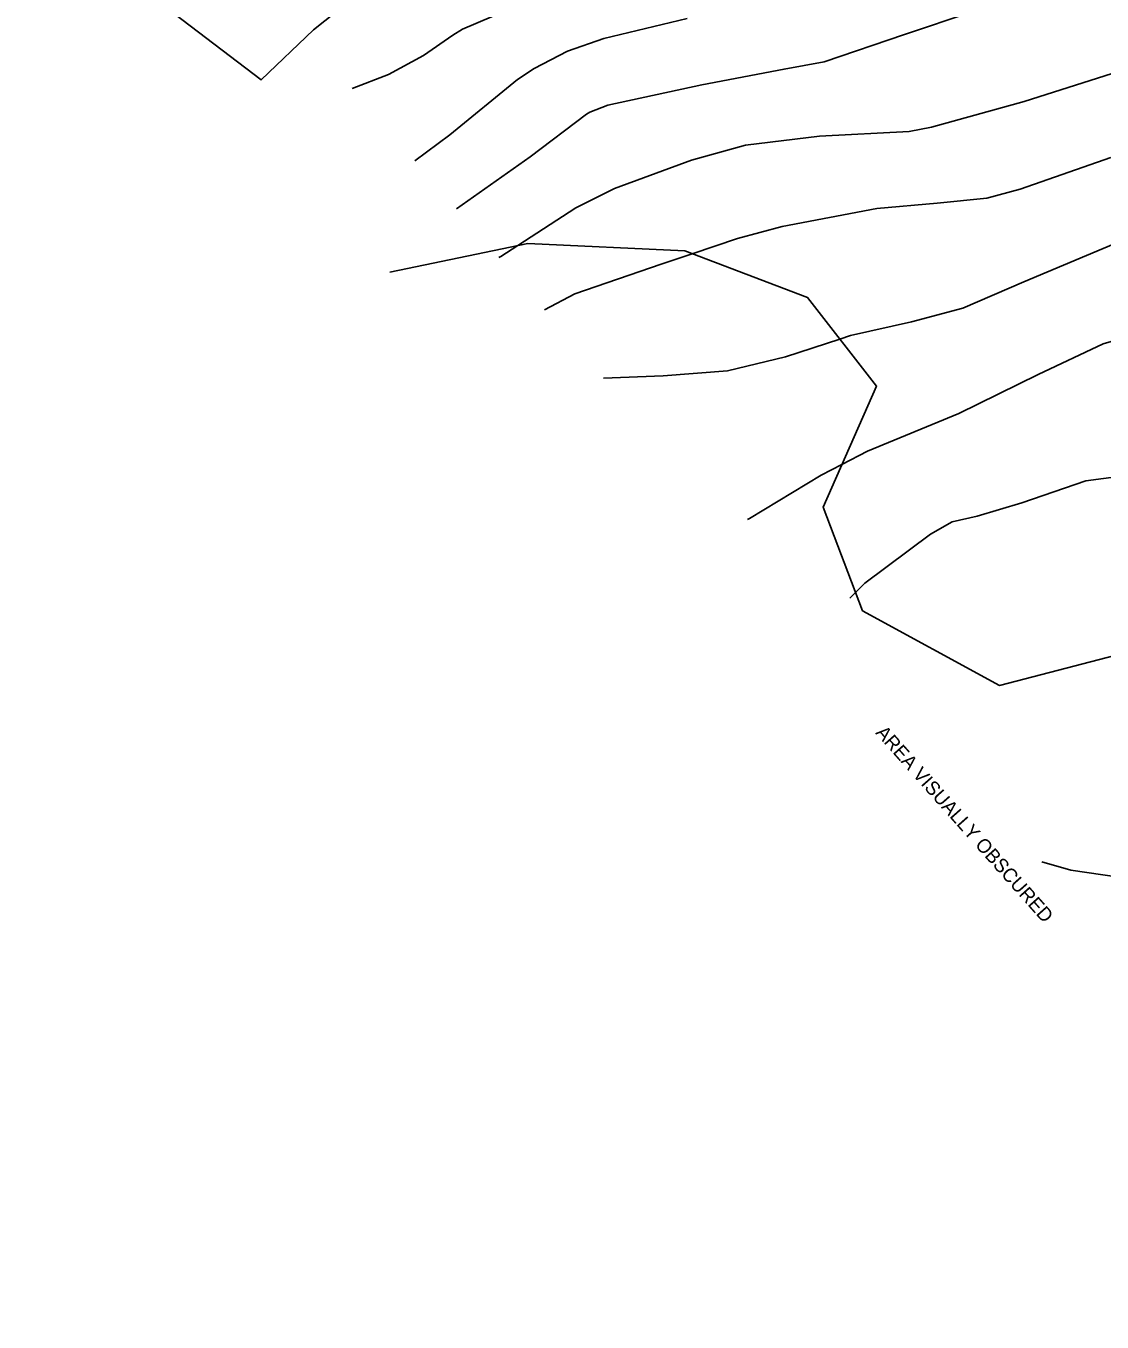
# Model space of a CAD drawing. Extents: x 1467615 to 2003689, y 770235 to 1108726.
# Drawn here: x 2001144.6 to 2001299.4, y 772389.6 to 772576.2 of the extents above; entities that cross this region are included whole.
import ezdxf

# ---------------------------------------------------------------- set-up
doc = ezdxf.new("R2010")
doc.units = 0
for name, color, linetype in [('RD_DTM_Major1', 7, 'Continuous'), ('RD_DTM_Major2', 7, 'Continuous'), ('RD_DTM_Minor1', 7, 'Continuous'), ('RD_DTM_Minor2', 7, 'Continuous'), ('RD_DTM_Obscure', 7, 'Continuous'), ('RD_TX_Misc1', 7, 'Continuous')]:
    doc.layers.add(name, color=color, linetype=linetype)

msp = doc.modelspace()

# ---------------------------------------------------------------- linework, layer by layer
at = {"layer": 'RD_DTM_Major1'}
for points in [[(2001289.08, 772613), (2001287.09, 772612.04), (2001280.37, 772608.31), (2001275.34, 772604.71), (2001270.52, 772600.96), (2001262.48, 772596.45), (2001248.06, 772590.02), (2001240.13, 772587.01), (2001230.82, 772584.44), (2001218.34, 772580.43), (2001207.39, 772575.72), (2001205.99, 772574.87), (2001201.77, 772571.94), (2001196.72, 772569.21), (2001191.5, 772567.18)], [(2001341.33, 772552.53), (2001328.75, 772553), (2001322.36, 772552.97), (2001320.73, 772552.48), (2001312.82, 772549.46), (2001302.9, 772545.54), (2001288.15, 772539.36), (2001279.39, 772535.57), (2001271.99, 772533.59), (2001263.2, 772531.63), (2001261.68, 772531.12)]]:
    msp.add_lwpolyline(points, dxfattribs=at)
at = {"layer": 'RD_DTM_Major2'}
msp.add_lwpolyline([(2001261.68, 772531.12), (2001253.86, 772528.54), (2001245.52, 772526.55), (2001236.26, 772525.83), (2001227.69, 772525.5)], dxfattribs=at)
at = {"layer": 'RD_DTM_Minor1'}
for points in [[(2001325.17, 772580.36), (2001311.63, 772573.95), (2001300.84, 772569.33), (2001288.2, 772565.3), (2001274.85, 772561.6), (2001271.65, 772560.99), (2001258.75, 772560.3), (2001248.11, 772559.02), (2001240.32, 772556.85), (2001229.27, 772552.77), (2001223.69, 772550.03), (2001215.33, 772544.58)], [(2001239.7, 772577.24), (2001227.71, 772574.36), (2001222.48, 772572.55), (2001217.72, 772570.08), (2001215.29, 772568.46), (2001205.57, 772560.51), (2001200.55, 772556.75)], [(2001280.72, 772578.23), (2001270.98, 772574.98), (2001259.42, 772571.04), (2001253.67, 772569.99), (2001241.83, 772567.73), (2001228.3, 772564.78), (2001225.71, 772563.79), (2001225.24, 772563.47), (2001217.14, 772557.34), (2001206.54, 772549.85)], [(2001300.66, 772557.27), (2001287.61, 772552.69), (2001282.85, 772551.4), (2001275.67, 772550.7), (2001267.01, 772549.9), (2001253.4, 772547.33), (2001246.97, 772545.58), (2001240.42, 772543.4)], [(2001348.37, 772536.27), (2001347.8, 772536.15), (2001334.9, 772532.84), (2001327.02, 772531.43), (2001319.19, 772531.99), (2001311.84, 772532.5), (2001305.02, 772532.03), (2001299.58, 772530.42), (2001290.23, 772526), (2001278.78, 772520.39), (2001265.64, 772514.96), (2001261.97, 772513.05)], [(2001350.28, 772516.94), (2001350.28, 772516.94), (2001348.82, 772517.67), (2001346.88, 772517.58), (2001341.61, 772515.78), (2001331.24, 772511.9), (2001324.9, 772510.32), (2001319.67, 772509.99), (2001309.33, 772510.85), (2001302.17, 772511.38), (2001297.07, 772510.69), (2001287.89, 772507.53), (2001281.44, 772505.61), (2001277.83, 772504.81), (2001274.71, 772503.04), (2001265.29, 772495.97), (2001263.94, 772494.64)]]:
    msp.add_lwpolyline(points, dxfattribs=at)
at = {"layer": 'RD_DTM_Minor2'}
msp.add_line((2001263.94, 772494.64), (2001263.11, 772493.82), dxfattribs=at)
for points in [[(2001215.33, 772544.58), (2001212.9, 772542.99), (2001212.63, 772542.84)], [(2001240.42, 772543.4), (2001235.97, 772541.92), (2001223.55, 772537.63), (2001219.17, 772535.31)], [(2001261.97, 772513.05), (2001259, 772511.51), (2001248.69, 772505.31), (2001248.38, 772505.16)], [(2001290.73, 772455.85), (2001294.93, 772454.69), (2001308.39, 772452.7), (2001315.93, 772452.52), (2001319.91, 772453.63), (2001323.57, 772456.01), (2001325.77, 772458.86), (2001327.52, 772462.96)]]:
    msp.add_lwpolyline(points, dxfattribs=at)
at = {"layer": 'RD_DTM_Obscure'}
for points in [[(2001196.66, 772584.18), (2001185.93, 772575.64), (2001178.4, 772568.42), (2001144.58, 772594.23)], [(2001196.95, 772540.74), (2001216.8, 772544.89), (2001239.36, 772543.8), (2001257.05, 772537.08), (2001266.95, 772524.36), (2001259.27, 772506.93), (2001264.94, 772492), (2001284.65, 772481.26), (2001307.33, 772487.13), (2001325.18, 772477.3), (2001327.29, 772463.98), (2001333.42, 772436.8), (2001343.07, 772423.11), (2001344.01, 772406.94), (2001338.84, 772397.43), (2001328.95, 772389.62)]]:
    msp.add_lwpolyline(points, dxfattribs=at)

# ---------------------------------------------------------------- texts
at = {"layer": 'RD_TX_Misc1'}
msp.add_text('AREA VISUALLY OBSCURED', height=2, rotation=311.5526, dxfattribs=at).set_placement((2001266.73, 772474.39))

doc.saveas('drawing.dxf')
